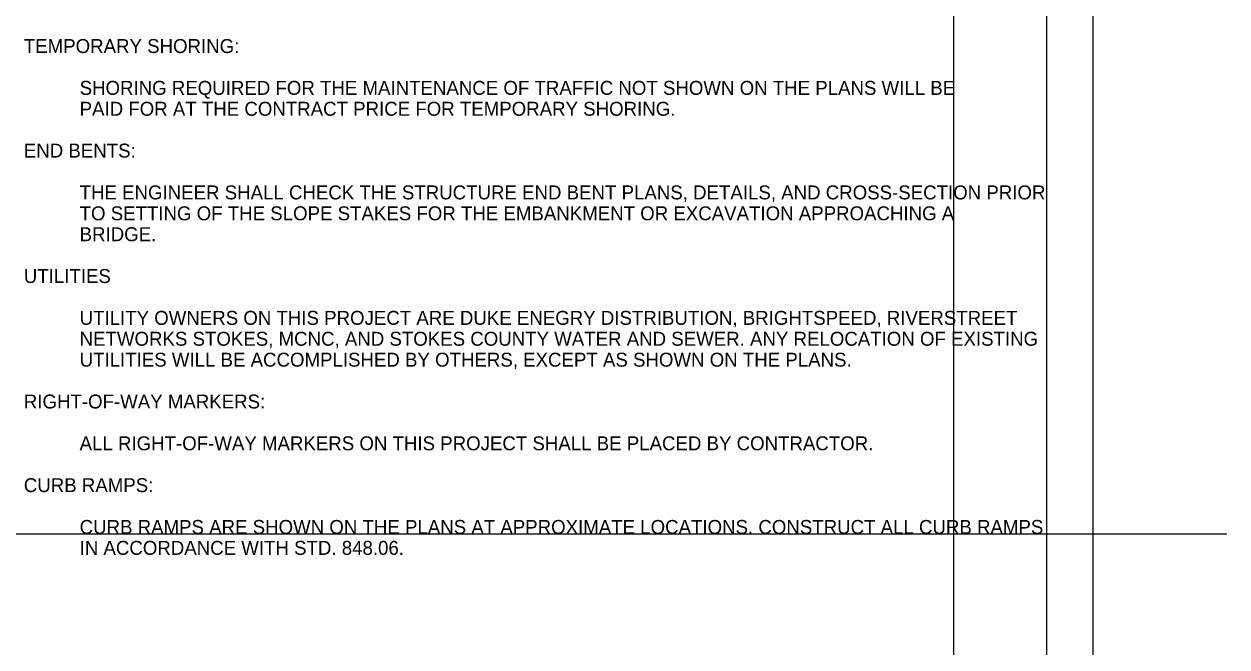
# Model space of a CAD drawing. Extents: x 573076.3 to 573113.7, y -55253.8 to -55199.3.
# Drawn here: x 573100.52 to 573113.45, y -55212.89 to -55206.19 of the extents above; entities that cross this region are included whole.
import ezdxf

# ---------------------------------------------------------------- set-up
doc = ezdxf.new("R2010")
doc.units = 0
for name, color, linetype in [('Prop DSN Text', 7, 'Continuous'), ('Scratch_Level_1', 7, 'Continuous'), ('Sheet Plan CELL', 7, 'Continuous'), ('Sheet Plot Border Inside CELL', 7, 'Continuous')]:
    doc.layers.add(name, color=color, linetype=linetype)

msp = doc.modelspace()

# ---------------------------------------------------------------- linework, layer by layer
at = {"layer": 'Scratch_Level_1'}
for p, q in [((573110.514, -55202.55), (573110.514, -55220.798)), ((573082.514, -55211.674), (573113.454, -55211.674))]:
    msp.add_line(p, q, dxfattribs=at)
at = {"layer": 'Sheet Plan CELL'}
msp.add_lwpolyline([(573081.514, -55199.798), (573111.514, -55199.798), (573111.514, -55220.798), (573081.514, -55220.798)], close=True, dxfattribs=at)
at = {"layer": 'Sheet Plot Border Inside CELL'}
msp.add_lwpolyline([(573112.014, -55199.298), (573078.014, -55199.298), (573078.014, -55221.298), (573112.014, -55221.298)], close=True, dxfattribs=at)

# ---------------------------------------------------------------- texts
at = {"layer": 'Prop DSN Text'}
for s, p in [('TEMPORARY SHORING:', (573100.514, -55206.5)), ('SHORING REQUIRED FOR THE MAINTENANCE OF TRAFFIC NOT SHOWN ON THE PLANS WILL BE', (573101.114, -55206.95)), ('PAID FOR AT THE CONTRACT PRICE FOR TEMPORARY SHORING.', (573101.114, -55207.175)), ('END BENTS:', (573100.514, -55207.625)), ('THE ENGINEER SHALL CHECK THE STRUCTURE END BENT PLANS, DETAILS, AND CROSS-SECTION PRIOR', (573101.114, -55208.075)), ('TO SETTING OF THE SLOPE STAKES FOR THE EMBANKMENT OR EXCAVATION APPROACHING A', (573101.114, -55208.3)), ('BRIDGE.', (573101.114, -55208.525)), ('UTILITIES', (573100.514, -55208.975)), ('UTILITY OWNERS ON THIS PROJECT ARE DUKE ENEGRY DISTRIBUTION, BRIGHTSPEED, RIVERSTREET', (573101.114, -55209.425)), ('NETWORKS STOKES, MCNC, AND STOKES COUNTY WATER AND SEWER. ANY RELOCATION OF EXISTING', (573101.114, -55209.65)), ('UTILITIES WILL BE ACCOMPLISHED BY OTHERS, EXCEPT AS SHOWN ON THE PLANS.', (573101.114, -55209.875)), ('RIGHT-OF-WAY MARKERS:', (573100.514, -55210.325)), ('ALL RIGHT-OF-WAY MARKERS ON THIS PROJECT SHALL BE PLACED BY CONTRACTOR.', (573101.114, -55210.775)), ('CURB RAMPS:', (573100.514, -55211.225)), ('CURB RAMPS ARE SHOWN ON THE PLANS AT APPROXIMATE LOCATIONS. CONSTRUCT ALL CURB RAMPS', (573101.114, -55211.675)), ('IN ACCORDANCE WITH STD. 848.06.', (573101.114, -55211.9))]:
    msp.add_text(s, height=0.15, dxfattribs=at).set_placement(p)

doc.saveas('drawing.dxf')
